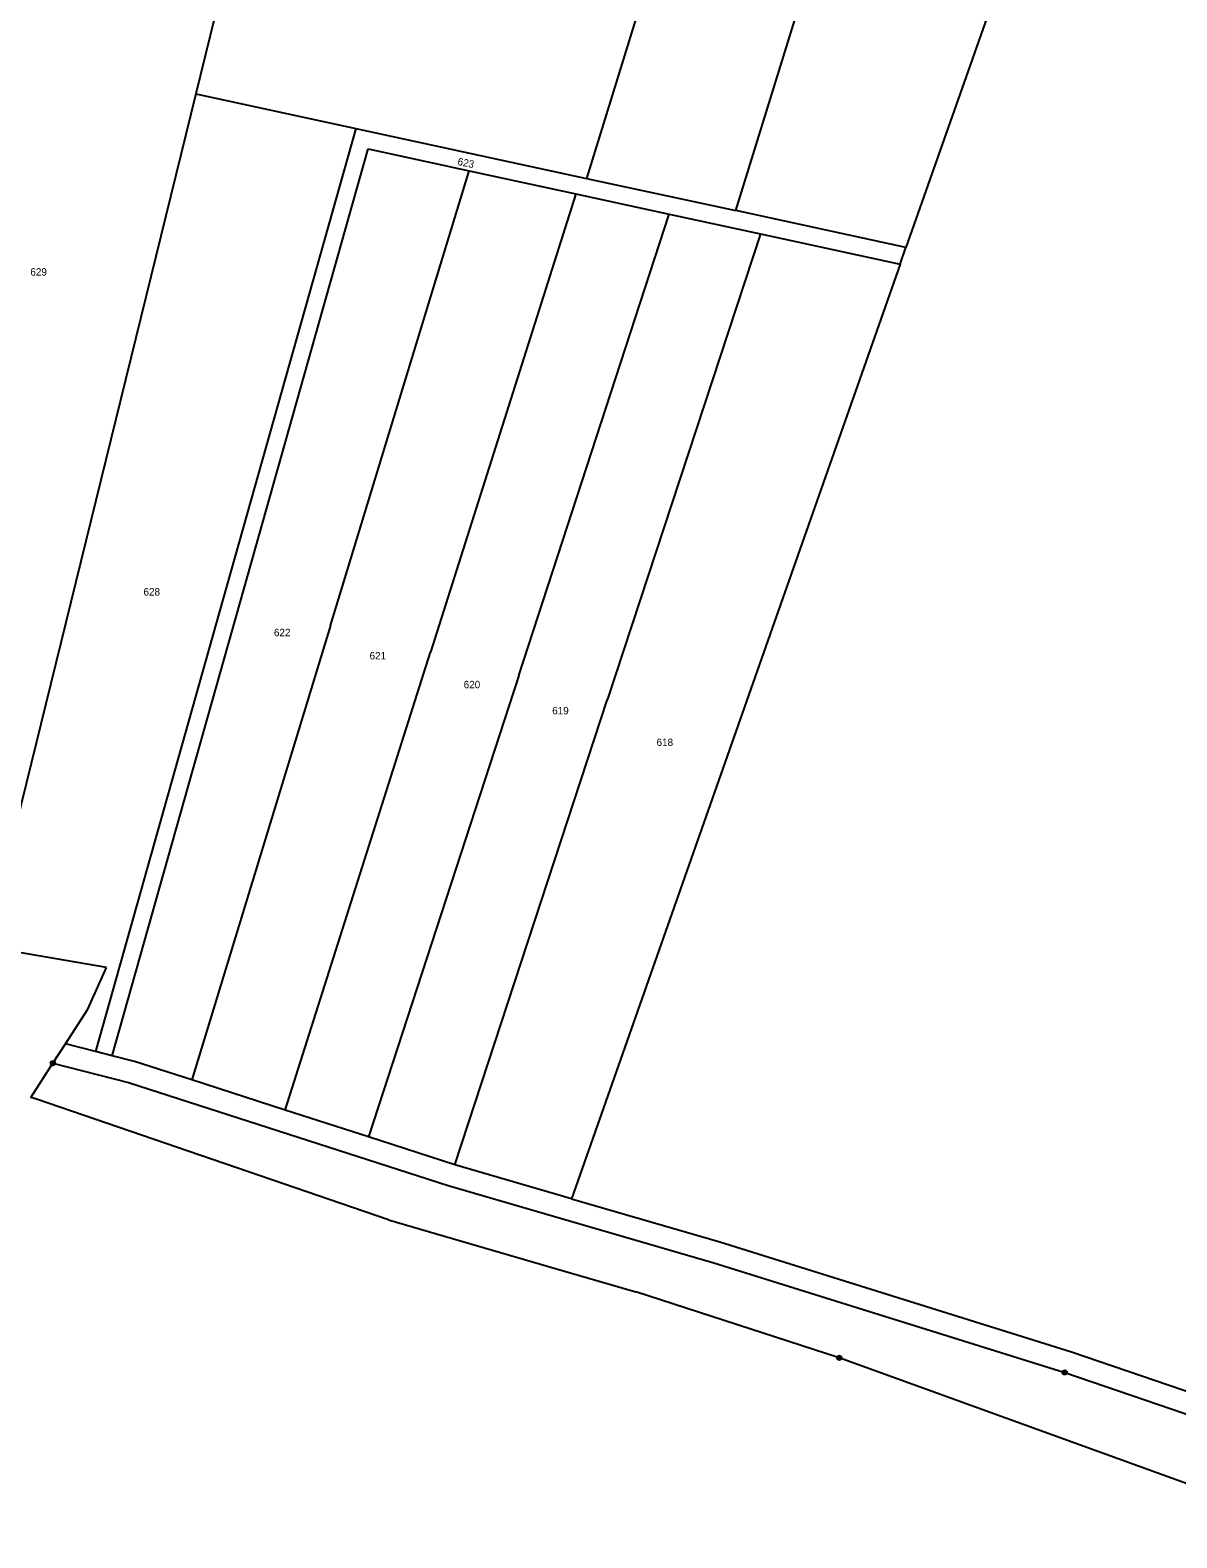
# Model space of a CAD drawing. Extents: x -759947 to -757003, y -1019641 to -1017100.
# Drawn here: x -759385.7 to -759122.9, y -1019298.1 to -1018952.6 of the extents above; entities that cross this region are included whole.
import ezdxf

# ---------------------------------------------------------------- set-up
doc = ezdxf.new("R2010")
doc.units = 0
doc.header["$LTSCALE"] = 0.68
doc.layers.add('1', color=7, linetype='Continuous', lineweight=25)
doc.layers.add('8', color=7, linetype='Continuous', lineweight=25)
doc.layers.add('2', color=7, linetype='Continuous')

msp = doc.modelspace()

# ---------------------------------------------------------------- linework, layer by layer
at = {"layer": '1'}
for p, q in [((-759223.95, -1018993.99), (-759171.46, -1018824.32)), ((-759127.1, -1018837.92), (-759184.98, -1019002.42)), ((-759216.51, -1018851.88), (-759258.18, -1018986.59)), ((-759326.75, -1018881.81), (-759347.77, -1018967.21)), ((-759347.77, -1018967.21), (-759374.13, -1019074.33)), ((-759347.77, -1018967.21), (-759311.09, -1018975.14)), ((-759311.09, -1018975.14), (-759341.47, -1019082.82)), ((-759311.09, -1018975.14), (-759258.18, -1018986.59)), ((-759337.57, -1019083.74), (-759308.26, -1018979.85)), ((-759308.26, -1018979.85), (-759285.08, -1018984.86)), ((-759316.89, -1019089), (-759285.08, -1018984.86)), ((-759285.08, -1018984.86), (-759260.61, -1018990.16)), ((-759258.18, -1018986.59), (-759223.95, -1018993.99)), ((-759260.61, -1018990.16), (-759293.92, -1019095.11)), ((-759260.61, -1018990.16), (-759239.23, -1018994.78)), ((-759273.71, -1019100.49), (-759239.23, -1018994.78)), ((-759239.23, -1018994.78), (-759218.31, -1018999.3)), ((-759184.98, -1019002.42), (-759223.95, -1018993.99)), ((-759218.31, -1018999.3), (-759253.35, -1019105.94)), ((-759218.31, -1018999.3), (-759186.31, -1019006.23)), ((-759186.31, -1019006.23), (-759184.98, -1019002.42)), ((-759186.31, -1019006.23), (-759224, -1019113.35)), ((-759374.13, -1019074.33), (-759395.85, -1019162.62)), ((-759341.47, -1019082.82), (-759370.76, -1019186.64)), ((-759366.89, -1019187.63), (-759337.57, -1019083.74)), ((-759316.89, -1019089), (-759348.69, -1019193.15)), ((-759327.23, -1019200.06), (-759293.92, -1019095.11)), ((-759273.71, -1019100.49), (-759308.19, -1019206.2)), ((-759288.38, -1019212.58), (-759253.35, -1019105.94)), ((-759224, -1019113.35), (-759261.65, -1019220.36)), ((-759368.2, -1019167.41), (-759395.85, -1019162.62)), ((-759372.51, -1019176.92), (-759368.2, -1019167.41)), ((-759377.65, -1019184.88), (-759372.51, -1019176.92)), ((-759380.51, -1019189.31), (-759377.65, -1019184.88)), ((-759370.76, -1019186.64), (-759377.65, -1019184.88)), ((-759366.89, -1019187.63), (-759370.76, -1019186.64)), ((-759361.8, -1019188.92), (-759366.89, -1019187.63)), ((-759385.55, -1019197.13), (-759380.51, -1019189.31)), ((-759380.51, -1019189.31), (-759363.19, -1019193.73)), ((-759348.69, -1019193.15), (-759361.8, -1019188.92)), ((-759363.19, -1019193.73), (-759289.87, -1019217.35)), ((-759327.23, -1019200.06), (-759348.69, -1019193.15)), ((-759384.24, -1019197.58), (-759385.55, -1019197.13)), ((-759303.56, -1019225.17), (-759384.24, -1019197.58)), ((-759308.19, -1019206.2), (-759327.23, -1019200.06)), ((-759288.38, -1019212.58), (-759308.19, -1019206.2)), ((-759261.65, -1019220.36), (-759288.38, -1019212.58)), ((-759289.87, -1019217.35), (-759229.05, -1019235.05)), ((-759261.65, -1019220.36), (-759227.65, -1019230.25)), ((-759303.56, -1019225.17), (-759263.21, -1019236.92)), ((-759227.65, -1019230.25), (-759147.02, -1019255.41)), ((-759229.05, -1019235.05), (-759148.58, -1019260.16)), ((-759263.21, -1019236.92), (-759246.89, -1019241.68)), ((-759200.26, -1019256.81), (-759246.89, -1019241.68)), ((-759111.27, -1019289.05), (-759200.26, -1019256.81)), ((-759147.02, -1019255.41), (-759074.05, -1019280.46)), ((-759148.58, -1019260.16), (-759038.18, -1019298.05))]:
    msp.add_line(p, q, dxfattribs=at)
at = {"layer": '8'}
for centre, radius in [((-759380.51, -1019189.3099), 0.5), ((-759380.51, -1019189.3099), 0.0303), ((-759200.26, -1019256.8099), 0.5), ((-759200.26, -1019256.8099), 0.0303), ((-759148.58, -1019260.1599), 0.5), ((-759148.58, -1019260.1599), 0.0303)]:
    msp.add_circle(centre, radius, dxfattribs=at)

# ---------------------------------------------------------------- texts
at = {"layer": '2'}
msp.add_text('623', height=1.7, rotation=348, dxfattribs=at).set_placement((-759287.868, -1018983.485))
for s, p in [('629', (-759385.67, -1019008.875)), ('628', (-759359.74, -1019082.165)), ('622', (-759329.84, -1019091.485)), ('621', (-759307.92, -1019096.805)), ('620', (-759286.35, -1019103.405)), ('619', (-759266.06, -1019109.385)), ('618', (-759242.14, -1019116.655))]:
    msp.add_text(s, height=1.7, dxfattribs=at).set_placement(p)

doc.saveas('drawing.dxf')
